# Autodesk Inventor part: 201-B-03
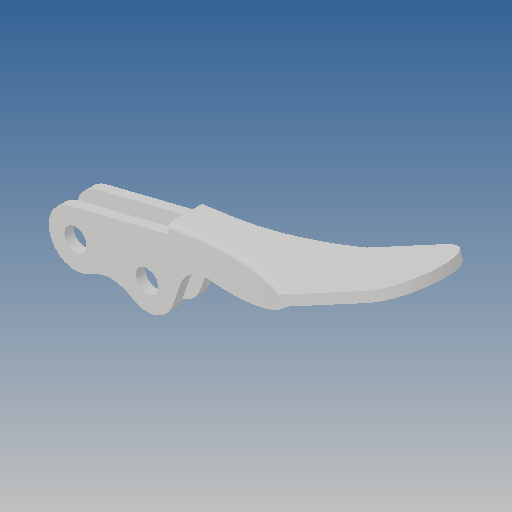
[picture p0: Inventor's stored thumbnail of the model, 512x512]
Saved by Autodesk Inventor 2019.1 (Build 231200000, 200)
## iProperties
Created: 2012-01
Part Number: 201-B-03
Material: Ogólny
Document SubType Name: Modeling
Designer: CADENGINEERING4
Density: 1 g/cm^3
Appearance: Domyślna
Author: CADENGINEERING4
Revision Number: ÈÎºÎ
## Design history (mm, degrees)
feature "ÇÐ³ý-À­Éì3"
node "Bryła1"
